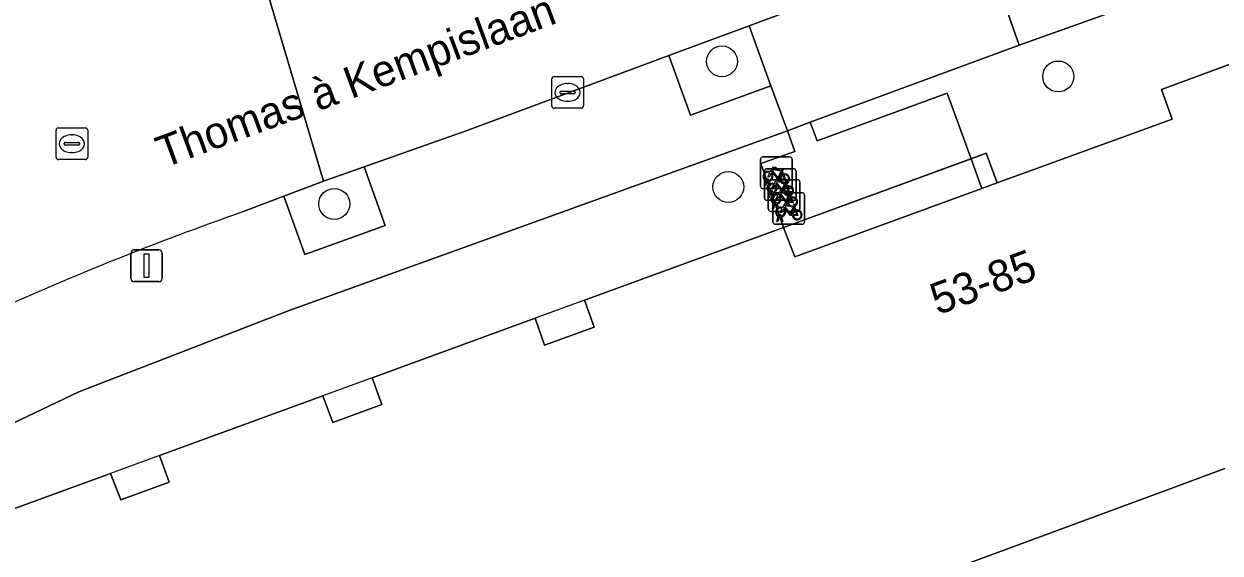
# Model space of a CAD drawing. Extents: x 162523 to 163266, y 381230 to 382050.
# Drawn here: x 162737.39 to 162775.21, y 381701.94 to 381718.66 of the extents above; entities that cross this region are included whole.
import ezdxf

# ---------------------------------------------------------------- set-up
doc = ezdxf.new("R2010")
doc.units = 0
for name, color, linetype in [('IMGEO_Boom', 7, 'Continuous'), ('IMGEO_Erf', 7, 'Continuous'), ('IMGEO_Fietsenrek', 7, 'Continuous'), ('IMGEO_Groenvoorziening', 7, 'Continuous'), ('IMGEO_Kolk', 7, 'Continuous'), ('IMGEO_Lichtmast', 7, 'Continuous'), ('IMGEO_Openbare_ruimte_label', 7, 'Continuous'), ('IMGEO_Pand', 7, 'Continuous'), ('IMGEO_Pand_nummerreeks', 7, 'Continuous'), ('IMGEO_Pand_overbouw', 7, 'Continuous'), ('IMGEO_Rijbaan_lokaal_open', 7, 'Continuous'), ('IMGEO_Rioolput', 7, 'Continuous'), ('IMGEO_Voetpad_open', 7, 'Continuous')]:
    doc.layers.add(name, color=color, linetype=linetype)

msp = doc.modelspace()

# ---------------------------------------------------------------- linework, layer by layer
at = {"layer": 'IMGEO_Boom'}
for centre in [(162759.459, 381717.482), (162770.09, 381717.004), (162759.66, 381713.512), (162747.201, 381712.976)]:
    msp.add_circle(centre, 0.489, dxfattribs=at)
at = {"layer": 'IMGEO_Erf'}
for points in [[(162778.489, 381721.436), (162768.851, 381717.989), (162762.252, 381715.555), (162762.466, 381714.975), (162766.58, 381716.476), (162767.337, 381714.403), (162767.817, 381714.579), (162768.163, 381713.64), (162773.695, 381715.655), (162773.351, 381716.588), (162780.839, 381719.349)], [(162775.358, 381704.61), (162773.427, 381703.898), (162759.719, 381698.841), (162761.312, 381694.398), (162763.112, 381689.257), (162762.115, 381688.89), (162763.84, 381684.24), (162762.819, 381683.875), (162763.711, 381681.402), (162763.98, 381680.658), (162756.398, 381677.905), (162755.212, 381681.19), (162747.24, 381678.307), (162791.576, 381640.722)]]:
    msp.add_lwpolyline(points, dxfattribs=at)
msp.add_lwpolyline([(162753.556, 381709.363), (162753.844, 381708.508), (162755.423, 381709.086), (162755.114, 381709.931), (162761.409, 381712.234), (162760.693, 381714.258), (162761.766, 381714.631), (162761.529, 381715.288), (162745.777, 381709.607), (162739.121, 381707.042), (162734.235, 381704.704), (162734.45, 381704.133), (162734.977, 381702.577), (162740.13, 381704.457), (162740.453, 381703.623), (162741.985, 381704.181), (162741.677, 381705.026), (162746.839, 381706.907), (162747.158, 381706.066), (162748.708, 381706.633), (162748.399, 381707.478)], close=True, dxfattribs=at)
at = {"layer": 'IMGEO_Fietsenrek'}
for p, q in [((162760.677, 381713.538), (162760.677, 381714.379)), ((162760.677, 381714.379), (162760.677, 381713.538)), ((162760.752, 381714.463), (162761.593, 381714.463)), ((162761.593, 381714.463), (162760.752, 381714.463)), ((162761.677, 381714.388), (162761.677, 381713.547)), ((162761.677, 381713.547), (162761.677, 381714.388)), ((162760.8, 381713.165), (162760.8, 381714.006)), ((162760.8, 381714.006), (162760.8, 381713.165)), ((162760.875, 381714.09), (162761.716, 381714.09)), ((162761.716, 381714.09), (162760.875, 381714.09)), ((162761.364, 381714.012), (162761.4, 381713.917)), ((162761.8, 381714.015), (162761.8, 381713.174)), ((162761.8, 381713.174), (162761.8, 381714.015)), ((162760.804, 381713.547), (162760.843, 381713.707)), ((162760.873, 381713.695), (162760.838, 381713.547)), ((162760.915, 381713.719), (162760.914, 381713.723)), ((162760.956, 381713.547), (162760.922, 381713.689)), ((162760.925, 381712.814), (162760.925, 381713.655)), ((162760.925, 381713.655), (162760.925, 381712.814)), ((162760.946, 381713.73), (162760.947, 381713.723)), ((162760.954, 381713.693), (162760.989, 381713.547)), ((162761, 381713.739), (162761.841, 381713.739)), ((162761.841, 381713.739), (162761, 381713.739)), ((162761.487, 381713.639), (162761.523, 381713.544)), ((162761.925, 381713.664), (162761.925, 381712.823)), ((162761.925, 381712.823), (162761.925, 381713.664)), ((162761.602, 381713.463), (162760.761, 381713.463)), ((162760.761, 381713.463), (162761.602, 381713.463)), ((162760.838, 381713.547), (162760.804, 381713.547)), ((162760.927, 381713.174), (162760.966, 381713.334)), ((162760.989, 381713.547), (162760.956, 381713.547)), ((162760.996, 381713.322), (162760.961, 381713.174)), ((162761.038, 381713.346), (162761.037, 381713.35)), ((162761.079, 381713.174), (162761.045, 381713.316)), ((162761.069, 381713.357), (162761.07, 381713.35)), ((162761.069, 381712.407), (162761.069, 381713.248)), ((162761.069, 381713.248), (162761.069, 381712.407)), ((162761.077, 381713.32), (162761.112, 381713.174)), ((162761.144, 381713.332), (162761.985, 381713.332)), ((162761.985, 381713.332), (162761.144, 381713.332)), ((162761.612, 381713.288), (162761.648, 381713.193)), ((162762.069, 381713.257), (162762.069, 381712.416)), ((162762.069, 381712.416), (162762.069, 381713.257)), ((162761.725, 381713.09), (162760.884, 381713.09)), ((162760.884, 381713.09), (162761.725, 381713.09)), ((162760.961, 381713.174), (162760.927, 381713.174)), ((162761.052, 381712.823), (162761.091, 381712.983)), ((162761.086, 381712.823), (162761.052, 381712.823)), ((162761.112, 381713.174), (162761.079, 381713.174)), ((162761.121, 381712.971), (162761.086, 381712.823)), ((162761.163, 381712.995), (162761.162, 381712.999)), ((162761.204, 381712.823), (162761.17, 381712.965)), ((162761.194, 381713.006), (162761.195, 381712.999)), ((162761.202, 381712.969), (162761.237, 381712.823)), ((162761.237, 381712.823), (162761.204, 381712.823)), ((162761.756, 381712.881), (162761.792, 381712.786)), ((162761.85, 381712.739), (162761.009, 381712.739)), ((162761.009, 381712.739), (162761.85, 381712.739)), ((162761.196, 381712.416), (162761.235, 381712.576)), ((162761.265, 381712.564), (162761.23, 381712.416)), ((162761.307, 381712.588), (162761.306, 381712.592)), ((162761.348, 381712.416), (162761.314, 381712.558)), ((162761.338, 381712.599), (162761.339, 381712.592)), ((162761.346, 381712.562), (162761.381, 381712.416)), ((162761.994, 381712.332), (162761.153, 381712.332)), ((162761.153, 381712.332), (162761.994, 381712.332)), ((162761.23, 381712.416), (162761.196, 381712.416)), ((162761.381, 381712.416), (162761.348, 381712.416))]:
    msp.add_line(p, q, dxfattribs=at)
for points in [[(162761.011, 381713.937), (162760.959, 381713.847), (162760.919, 381713.822), (162760.92, 381713.869), (162760.975, 381713.963)], [(162760.99, 381713.989), (162761.085, 381714.153), (162761.171, 381714.139), (162761.173, 381714.13), (162761.117, 381714.119), (162761.09, 381714.074), (162761.346, 381714.033)], [(162761.286, 381713.745), (162761.236, 381713.745), (162761.045, 381713.996), (162761.026, 381713.964)], [(162761.333, 381714.008), (162761.076, 381714.049), (162761.059, 381714.02), (162761.226, 381713.8), (162761.333, 381714.008)], [(162761.381, 381713.91), (162761.351, 381713.987), (162761.242, 381713.769), (162761.285, 381713.769)], [(162761.346, 381714.033), (162761.371, 381714.082), (162761.365, 381714.086), (162761.342, 381714.09), (162761.33, 381714.097), (162761.329, 381714.1), (162761.331, 381714.105), (162761.426, 381714.09), (162761.428, 381714.08), (162761.418, 381714.067), (162761.406, 381714.061), (162761.392, 381714.067), (162761.364, 381714.012)], [(162761.134, 381713.564), (162761.082, 381713.474), (162761.042, 381713.449), (162761.043, 381713.496), (162761.098, 381713.59)], [(162761.113, 381713.616), (162761.208, 381713.78), (162761.294, 381713.766), (162761.296, 381713.757), (162761.24, 381713.746), (162761.213, 381713.701), (162761.469, 381713.66)], [(162761.409, 381713.372), (162761.359, 381713.372), (162761.168, 381713.623), (162761.149, 381713.591)], [(162761.456, 381713.635), (162761.199, 381713.676), (162761.182, 381713.647), (162761.349, 381713.427), (162761.456, 381713.635)], [(162761.315, 381713.769), (162761.435, 381713.768), (162761.391, 381713.882)], [(162761.411, 381713.889), (162761.466, 381713.744), (162761.316, 381713.744)], [(162761.504, 381713.537), (162761.474, 381713.614), (162761.365, 381713.396), (162761.408, 381713.396)], [(162761.469, 381713.66), (162761.494, 381713.709), (162761.488, 381713.713), (162761.465, 381713.717), (162761.453, 381713.724), (162761.452, 381713.727), (162761.454, 381713.732), (162761.549, 381713.717), (162761.551, 381713.707), (162761.541, 381713.694), (162761.529, 381713.688), (162761.515, 381713.694), (162761.487, 381713.639)], [(162761.259, 381713.213), (162761.207, 381713.123), (162761.167, 381713.098), (162761.168, 381713.145), (162761.223, 381713.239)], [(162761.238, 381713.265), (162761.333, 381713.429), (162761.419, 381713.415), (162761.421, 381713.406), (162761.365, 381713.395), (162761.338, 381713.35), (162761.594, 381713.309)], [(162761.534, 381713.021), (162761.484, 381713.021), (162761.293, 381713.272), (162761.274, 381713.24)], [(162761.581, 381713.284), (162761.324, 381713.325), (162761.307, 381713.296), (162761.474, 381713.076), (162761.581, 381713.284)], [(162761.438, 381713.396), (162761.558, 381713.395), (162761.514, 381713.509)], [(162761.534, 381713.516), (162761.589, 381713.371), (162761.439, 381713.371)], [(162761.629, 381713.186), (162761.599, 381713.263), (162761.49, 381713.045), (162761.533, 381713.045)], [(162761.594, 381713.309), (162761.619, 381713.358), (162761.613, 381713.362), (162761.59, 381713.366), (162761.578, 381713.373), (162761.577, 381713.376), (162761.579, 381713.381), (162761.674, 381713.366), (162761.676, 381713.356), (162761.666, 381713.343), (162761.654, 381713.337), (162761.64, 381713.343), (162761.612, 381713.288)], [(162761.403, 381712.806), (162761.351, 381712.716), (162761.311, 381712.691), (162761.312, 381712.738), (162761.367, 381712.832)], [(162761.382, 381712.858), (162761.477, 381713.022), (162761.563, 381713.008), (162761.565, 381712.999), (162761.509, 381712.988), (162761.482, 381712.943), (162761.738, 381712.902)], [(162761.678, 381712.614), (162761.628, 381712.614), (162761.437, 381712.865), (162761.418, 381712.833)], [(162761.725, 381712.877), (162761.468, 381712.918), (162761.451, 381712.889), (162761.618, 381712.669), (162761.725, 381712.877)], [(162761.563, 381713.045), (162761.683, 381713.044), (162761.639, 381713.158)], [(162761.659, 381713.165), (162761.714, 381713.02), (162761.564, 381713.02)], [(162761.773, 381712.779), (162761.743, 381712.856), (162761.634, 381712.638), (162761.677, 381712.638)], [(162761.738, 381712.902), (162761.763, 381712.951), (162761.757, 381712.955), (162761.734, 381712.959), (162761.722, 381712.966), (162761.721, 381712.969), (162761.723, 381712.974), (162761.818, 381712.959), (162761.82, 381712.949), (162761.81, 381712.936), (162761.798, 381712.93), (162761.784, 381712.936), (162761.756, 381712.881)], [(162761.707, 381712.638), (162761.827, 381712.637), (162761.783, 381712.751)], [(162761.803, 381712.758), (162761.858, 381712.613), (162761.708, 381712.613)]]:
    msp.add_lwpolyline(points, dxfattribs=at)
for centre, radius, start, end in [((162760.755, 381714.385), 0.0779, 92.4484, 184.2845), ((162760.755, 381714.385), 0.0779, 92.4484, 184.2845), ((162761.599, 381714.385), 0.0779, 2.4484, 94.2845), ((162761.599, 381714.385), 0.0779, 2.4484, 94.2845), ((162760.917, 381713.848), 0.159, 62.6766, 242.1369), ((162760.917, 381713.848), 0.129, 63.3192, 238.903), ((162760.878, 381714.012), 0.0779, 92.4484, 184.2845), ((162760.878, 381714.012), 0.0779, 92.4484, 184.2845), ((162760.917, 381713.848), 0.159, 283.5766, 46.6042), ((162761.722, 381714.012), 0.0779, 2.4484, 94.2845), ((162761.722, 381714.012), 0.0779, 2.4484, 94.2845), ((162760.897, 381713.719), 0.0499, 12.8025, 158.6934), ((162760.917, 381713.848), 0.159, 253.9967, 271.7867), ((162760.897, 381713.719), 0.0174, 12.8025, 163.4502), ((162760.917, 381713.848), 0.129, 253.415, 269.0204), ((162761.04, 381713.475), 0.159, 62.6766, 242.1369), ((162761.04, 381713.475), 0.129, 63.3192, 238.903), ((162761.003, 381713.661), 0.0779, 92.4484, 184.2845), ((162761.003, 381713.661), 0.0779, 92.4484, 184.2845), ((162760.917, 381713.848), 0.129, 283.6043, 43.4302), ((162761.04, 381713.475), 0.159, 283.5766, 46.6042), ((162761.444, 381713.764), 0.159, 113.3408, 178.3217), ((162761.444, 381713.764), 0.159, 187.0065, 105.7708), ((162761.444, 381713.764), 0.129, 113.923, 177.9556), ((162761.444, 381713.764), 0.129, 188.6715, 104.5883), ((162761.847, 381713.661), 0.0779, 2.4484, 94.2845), ((162761.847, 381713.661), 0.0779, 2.4484, 94.2845), ((162760.755, 381713.541), 0.0779, 182.4484, 274.2845), ((162760.755, 381713.541), 0.0779, 182.4484, 274.2845), ((162761.02, 381713.346), 0.0499, 12.8025, 158.6934), ((162761.04, 381713.475), 0.159, 253.9967, 271.7867), ((162761.02, 381713.346), 0.0174, 12.8025, 163.4502), ((162761.04, 381713.475), 0.129, 253.415, 269.0204), ((162761.165, 381713.124), 0.159, 62.6766, 242.1369), ((162761.165, 381713.124), 0.129, 63.3192, 238.903), ((162761.147, 381713.254), 0.0779, 92.4484, 184.2845), ((162761.147, 381713.254), 0.0779, 92.4484, 184.2845), ((162761.04, 381713.475), 0.129, 283.6043, 43.4302), ((162761.165, 381713.124), 0.129, 283.6043, 43.4302), ((162761.165, 381713.124), 0.159, 283.5766, 46.6042), ((162761.567, 381713.391), 0.159, 113.3408, 178.3217), ((162761.567, 381713.391), 0.159, 187.0065, 105.7708), ((162761.567, 381713.391), 0.129, 113.923, 177.9556), ((162761.567, 381713.391), 0.129, 188.6715, 104.5883), ((162761.599, 381713.541), 0.0779, 272.4484, 4.2845), ((162761.599, 381713.541), 0.0779, 272.4484, 4.2845), ((162761.991, 381713.254), 0.0779, 2.4484, 94.2845), ((162761.991, 381713.254), 0.0779, 2.4484, 94.2845), ((162760.878, 381713.168), 0.0779, 182.4484, 274.2845), ((162760.878, 381713.168), 0.0779, 182.4484, 274.2845), ((162761.145, 381712.995), 0.0499, 12.8025, 158.6934), ((162761.165, 381713.124), 0.159, 253.9967, 271.7867), ((162761.145, 381712.995), 0.0174, 12.8025, 163.4502), ((162761.165, 381713.124), 0.129, 253.415, 269.0204), ((162761.309, 381712.717), 0.159, 62.6766, 242.1369), ((162761.309, 381712.717), 0.129, 63.3192, 238.903), ((162761.309, 381712.717), 0.159, 283.5766, 46.6042), ((162761.692, 381713.04), 0.159, 113.3408, 178.3217), ((162761.692, 381713.04), 0.159, 187.0065, 105.7708), ((162761.692, 381713.04), 0.129, 113.923, 177.9556), ((162761.692, 381713.04), 0.129, 188.6715, 104.5883), ((162761.722, 381713.168), 0.0779, 272.4484, 4.2845), ((162761.722, 381713.168), 0.0779, 272.4484, 4.2845), ((162761.847, 381712.817), 0.0779, 272.4484, 4.2845), ((162761.847, 381712.817), 0.0779, 272.4484, 4.2845), ((162761.003, 381712.817), 0.0779, 182.4484, 274.2845), ((162761.003, 381712.817), 0.0779, 182.4484, 274.2845), ((162761.289, 381712.588), 0.0499, 12.8025, 158.6934), ((162761.309, 381712.717), 0.159, 253.9967, 271.7867), ((162761.289, 381712.588), 0.0174, 12.8025, 163.4502), ((162761.309, 381712.717), 0.129, 253.415, 269.0204), ((162761.309, 381712.717), 0.129, 283.6043, 43.4302), ((162761.836, 381712.633), 0.159, 113.3408, 178.3217), ((162761.836, 381712.633), 0.159, 187.0065, 105.7708), ((162761.836, 381712.633), 0.129, 113.923, 177.9556), ((162761.836, 381712.633), 0.129, 188.6715, 104.5883), ((162761.147, 381712.41), 0.0779, 182.4484, 274.2845), ((162761.147, 381712.41), 0.0779, 182.4484, 274.2845), ((162761.991, 381712.41), 0.0779, 272.4484, 4.2845), ((162761.991, 381712.41), 0.0779, 272.4484, 4.2845)]:
    msp.add_arc(centre, radius, start, end, dxfattribs=at)
at = {"layer": 'IMGEO_Groenvoorziening'}
for points in [[(162757.781, 381717.663), (162758.468, 381715.785), (162761.006, 381716.713), (162760.315, 381718.601)], [(162745.607, 381713.218), (162746.267, 381711.381), (162748.815, 381712.296), (162748.15, 381714.148), (162746.861, 381713.692)]]:
    msp.add_lwpolyline(points, close=True, dxfattribs=at)
at = {"layer": 'IMGEO_Kolk'}
for p, q in [((162754.153, 381717), (162755.005, 381717)), ((162754.078, 381716.074), (162754.078, 381716.926)), ((162754.566, 381716.78), (162754.591, 381716.78)), ((162755.079, 381716.926), (162755.079, 381716.074)), ((162754.337, 381716.494), (162754.337, 381716.506)), ((162754.775, 381716.457), (162754.377, 381716.457)), ((162754.38, 381716.543), (162754.778, 381716.543)), ((162754.821, 381716.506), (162754.821, 381716.494)), ((162755.005, 381716), (162754.153, 381716)), ((162754.589, 381716.22), (162754.564, 381716.22))]:
    msp.add_line(p, q, dxfattribs=at)
for points in [[(162754.153, 381717), (162755.005, 381717)], [(162754.078, 381716.074), (162754.078, 381716.926)], [(162755.079, 381716.926), (162755.079, 381716.074)], [(162755.005, 381716), (162754.153, 381716)]]:
    msp.add_lwpolyline(points, dxfattribs=at)
for centre, radius, start, end in [((162754.155, 381716.924), 0.0765, 91.552, 178.448), ((162754.155, 381716.924), 0.0765, 91.552, 178.448), ((162755.003, 381716.924), 0.0765, 1.552, 88.448), ((162755.003, 381716.924), 0.0765, 1.552, 88.448), ((162754.377, 381716.503), 0.0403, 85.8775, 175.7526), ((162754.374, 381716.493), 0.0366, 178.938, 274.7102), ((162754.778, 381716.5), 0.043, 264.8664, 352.4533), ((162754.782, 381716.505), 0.0386, 1.7309, 96.639), ((162754.155, 381716.076), 0.0765, 181.552, 268.448), ((162754.155, 381716.076), 0.0765, 181.552, 268.448), ((162755.003, 381716.076), 0.0765, 271.552, 358.448), ((162755.003, 381716.076), 0.0765, 271.552, 358.448)]:
    msp.add_arc(centre, radius, start, end, dxfattribs=at)
for centre, major_axis, ratio, start_param, end_param in [((162754.565, 381716.5), (-0.387, 0.002), 0.722429, 4.712389, 7.853982), ((162754.59, 381716.5), (-0.39, 0.002), 0.717154, 1.570796, 4.712389)]:
    msp.add_ellipse(centre, major_axis=major_axis, ratio=ratio, start_param=start_param, end_param=end_param, dxfattribs=at)
at = {"layer": 'IMGEO_Lichtmast'}
for p, q in [((162740.77, 381710.621), (162740.77, 381711.421)), ((162740.77, 381711.421), (162740.77, 381710.621)), ((162740.87, 381711.521), (162741.66, 381711.521)), ((162741.66, 381711.521), (162740.87, 381711.521)), ((162741.76, 381711.421), (162741.76, 381710.621)), ((162741.76, 381710.621), (162741.76, 381711.421)), ((162741.66, 381710.521), (162740.87, 381710.521)), ((162740.87, 381710.521), (162741.66, 381710.521))]:
    msp.add_line(p, q, dxfattribs=at)
msp.add_lwpolyline([(162741.19, 381711.396), (162741.34, 381711.396), (162741.34, 381710.646), (162741.19, 381710.646), (162741.19, 381711.396)], dxfattribs=at)
for centre, start, end in [((162740.87, 381711.421), 90, 180), ((162740.87, 381711.421), 90, 180), ((162741.66, 381711.421), 0, 90), ((162741.66, 381711.421), 360, 90), ((162740.87, 381710.621), 180, 270), ((162740.87, 381710.621), 180, 270), ((162741.66, 381710.621), 270, 0), ((162741.66, 381710.621), 270, 0)]:
    msp.add_arc(centre, 0.1, start, end, dxfattribs=at)
at = {"layer": 'IMGEO_Pand'}
for points in [[(162780.839, 381719.349), (162773.351, 381716.588), (162773.695, 381715.655), (162768.163, 381713.64), (162767.679, 381713.464), (162761.761, 381711.299), (162761.409, 381712.234), (162755.114, 381709.931), (162755.423, 381709.086), (162753.844, 381708.508), (162753.556, 381709.363), (162748.399, 381707.478), (162748.708, 381706.633), (162747.158, 381706.066), (162746.839, 381706.907), (162741.677, 381705.026), (162741.985, 381704.181), (162740.453, 381703.623), (162740.13, 381704.457), (162734.977, 381702.577)], [(162734.777, 381697.931), (162738.005, 381689.231), (162739.934, 381689.946), (162739.415, 381691.411), (162745.902, 381693.784), (162746.198, 381693.892), (162752.645, 381696.25), (162752.935, 381696.356), (162758.762, 381698.488), (162759.577, 381698.788), (162759.719, 381698.841), (162773.427, 381703.898), (162775.358, 381704.61)]]:
    msp.add_lwpolyline(points, dxfattribs=at)
at = {"layer": 'IMGEO_Pand_overbouw'}
for points in [[(162761.409, 381712.234), (162761.761, 381711.299), (162767.679, 381713.464), (162768.163, 381713.64), (162767.817, 381714.579)], [(162753.556, 381709.363), (162753.844, 381708.508), (162755.423, 381709.086), (162755.114, 381709.931)], [(162746.839, 381706.907), (162747.158, 381706.066), (162748.708, 381706.633), (162748.399, 381707.478)], [(162740.13, 381704.457), (162740.453, 381703.623), (162741.985, 381704.181), (162741.677, 381705.026)]]:
    msp.add_lwpolyline(points, close=True, dxfattribs=at)
at = {"layer": 'IMGEO_Rijbaan_lokaal_open'}
for points in [[(162816.425, 381743.491), (162804.215, 381739.844), (162789.911, 381735.529), (162787.126, 381734.714), (162786.892, 381734.638), (162766.566, 381727.391), (162747.636, 381720.644), (162745.077, 381719.704), (162746.861, 381713.692), (162748.15, 381714.148), (162751.373, 381715.289), (162757.781, 381717.663), (162760.315, 381718.601), (162762.482, 381719.404), (162766.087, 381720.739), (162767.355, 381721.2), (162767.683, 381721.314), (162770.249, 381722.202), (162772.973, 381723.146), (162774.09, 381723.533), (162775.256, 381723.963)], [(162744.3, 381712.723), (162745.607, 381713.218), (162746.861, 381713.692), (162745.077, 381719.704)]]:
    msp.add_lwpolyline(points, dxfattribs=at)
msp.add_arc((162777.795, 381617.507), 100.936, 109.38082, 114.20195, dxfattribs=at)
at = {"layer": 'IMGEO_Rioolput'}
for p, q in [((162738.405, 381714.453), (162738.405, 381715.305)), ((162738.48, 381715.379), (162739.332, 381715.379)), ((162738.893, 381715.159), (162738.918, 381715.159)), ((162739.406, 381715.305), (162739.406, 381714.453)), ((162738.664, 381714.873), (162738.664, 381714.885)), ((162739.102, 381714.836), (162738.704, 381714.836)), ((162738.707, 381714.922), (162739.105, 381714.922)), ((162739.148, 381714.885), (162739.148, 381714.873)), ((162739.332, 381714.379), (162738.48, 381714.379)), ((162738.916, 381714.599), (162738.891, 381714.599))]:
    msp.add_line(p, q, dxfattribs=at)
for points in [[(162738.405, 381714.453), (162738.405, 381715.305)], [(162738.48, 381715.379), (162739.332, 381715.379)], [(162739.406, 381715.305), (162739.406, 381714.453)], [(162739.332, 381714.379), (162738.48, 381714.379)]]:
    msp.add_lwpolyline(points, dxfattribs=at)
for centre, radius, start, end in [((162738.482, 381715.303), 0.0765, 91.552, 178.448), ((162738.482, 381715.303), 0.0765, 91.552, 178.448), ((162739.33, 381715.303), 0.0765, 1.552, 88.448), ((162739.33, 381715.303), 0.0765, 1.552, 88.448), ((162738.704, 381714.882), 0.0403, 85.8775, 175.7526), ((162738.701, 381714.872), 0.0366, 178.938, 274.7102), ((162739.105, 381714.879), 0.043, 264.8664, 352.4533), ((162739.109, 381714.884), 0.0386, 1.7309, 96.639), ((162738.482, 381714.455), 0.0765, 181.552, 268.448), ((162738.482, 381714.455), 0.0765, 181.552, 268.448), ((162739.33, 381714.455), 0.0765, 271.552, 358.448), ((162739.33, 381714.455), 0.0765, 271.552, 358.448)]:
    msp.add_arc(centre, radius, start, end, dxfattribs=at)
for centre, major_axis, ratio, start_param, end_param in [((162738.892, 381714.879), (-0.387, 0.002), 0.722429, 4.712389, 7.853982), ((162738.917, 381714.879), (-0.39, 0.002), 0.717154, 1.570796, 4.712389)]:
    msp.add_ellipse(centre, major_axis=major_axis, ratio=ratio, start_param=start_param, end_param=end_param, dxfattribs=at)
at = {"layer": 'IMGEO_Voetpad_open'}
for points in [[(162775.256, 381723.963), (162774.09, 381723.533), (162772.973, 381723.146), (162773.711, 381721.304), (162770.895, 381720.292), (162770.249, 381722.202), (162767.683, 381721.314), (162768.851, 381717.989), (162778.489, 381721.436), (162783.015, 381723.019)], [(162734.45, 381704.133), (162734.235, 381704.704), (162739.121, 381707.042), (162745.777, 381709.607), (162761.529, 381715.288), (162761.006, 381716.713), (162758.468, 381715.785), (162757.781, 381717.663), (162751.373, 381715.289), (162748.15, 381714.148), (162748.815, 381712.296), (162746.267, 381711.381), (162745.607, 381713.218), (162744.3, 381712.723)]]:
    msp.add_lwpolyline(points, dxfattribs=at)
for points in [[(162762.482, 381719.404), (162760.315, 381718.601), (162761.006, 381716.713), (162761.529, 381715.288), (162762.252, 381715.555), (162768.851, 381717.989), (162767.683, 381721.314), (162767.355, 381721.2), (162766.087, 381720.739)], [(162761.529, 381715.288), (162761.766, 381714.631), (162760.693, 381714.258), (162761.409, 381712.234), (162761.719, 381712.348), (162767.337, 381714.403), (162766.58, 381716.476), (162762.466, 381714.975), (162762.252, 381715.555)], [(162767.337, 381714.403), (162761.719, 381712.348), (162761.409, 381712.234), (162761.761, 381711.299), (162767.679, 381713.464)], [(162767.679, 381713.464), (162768.163, 381713.64), (162767.817, 381714.579), (162767.337, 381714.403)]]:
    msp.add_lwpolyline(points, close=True, dxfattribs=at)
msp.add_arc((162777.795, 381617.507), 100.936, 109.38082, 114.20195, dxfattribs=at)

# ---------------------------------------------------------------- texts
at = {"layer": 'IMGEO_Openbare_ruimte_label'}
msp.add_text('Thomas à Kempislaan', height=1, rotation=20.2475, dxfattribs=at).set_placement((162741.806, 381714.101))
at = {"layer": 'IMGEO_Pand_nummerreeks'}
msp.add_text('53-85', height=1, rotation=20.0504, dxfattribs=at).set_placement((162766.274, 381709.455))

doc.saveas('drawing.dxf')
